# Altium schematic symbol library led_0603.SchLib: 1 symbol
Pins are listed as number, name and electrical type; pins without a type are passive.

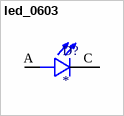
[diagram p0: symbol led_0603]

## led_0603
designator D?
LED Indication - Discrete 3.1V 0603 _1608 Metric_; MP: LTW-C191TLA; MF: Lite-On
footprint led_0603
pins: A, C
